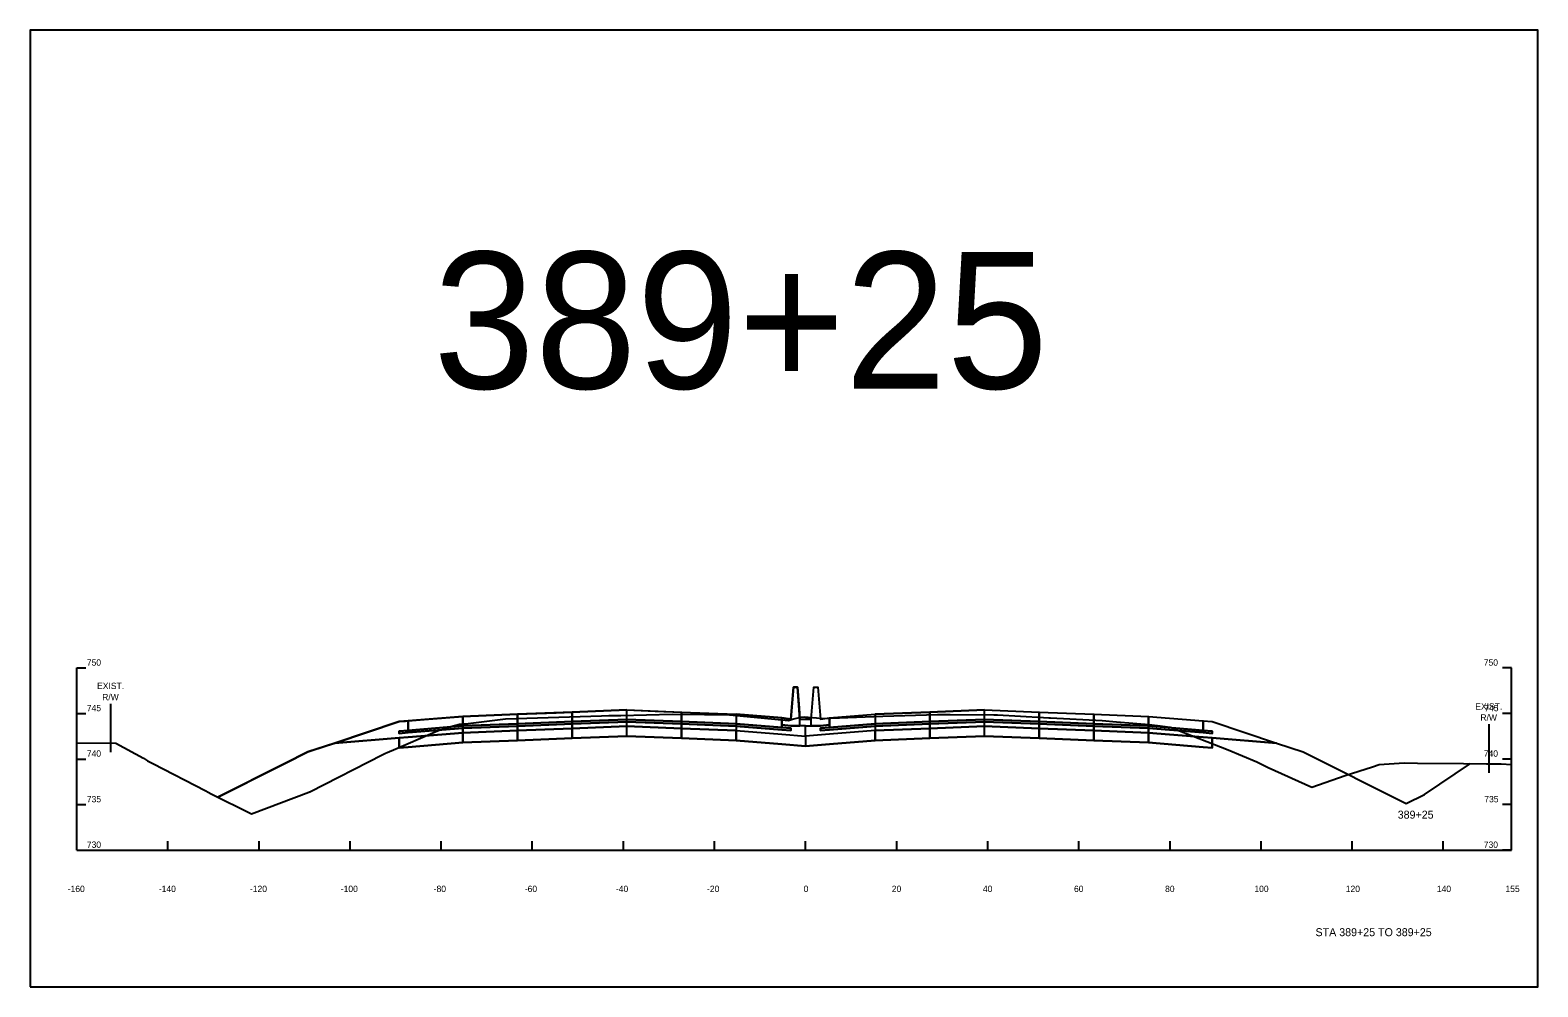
# Model space of a CAD drawing. Extents: x 0 to 2149228, y 0 to 2148913.
# Drawn here: x 2146915.4 to 2147246.4, y 2146375.1 to 2146585.1 of the extents above; entities that cross this region are included whole.
import ezdxf

# ---------------------------------------------------------------- set-up
doc = ezdxf.new("R2010")
doc.units = 0
for name, color, linetype in [('ADAMS CONST', 7, 'Continuous'), ('Default', 7, 'Continuous'), ('P_E_XS_Ground', 7, 'Continuous'), ('P_E_XS_RW', 7, 'Continuous'), ('P_MISC_TXT', 7, 'Continuous'), ('P_PROF_Grades', 7, 'Continuous'), ('P_RDWY_BarrierConc', 7, 'Continuous'), ('P_XS', 7, 'Continuous'), ('P_XS_Subgrade', 7, 'Continuous')]:
    doc.layers.add(name, color=color, linetype=linetype)

msp = doc.modelspace()

# ---------------------------------------------------------------- linework, layer by layer
at = {"layer": 'Default'}
msp.add_lwpolyline([(2146915.41, 2146375.06), (2147246.41, 2146375.06), (2147246.41, 2146585.06), (2146915.41, 2146585.06)], close=True, dxfattribs=at)
at = {"layer": 'P_E_XS_Ground'}
msp.add_lwpolyline([(2146925.66, 2146428.61), (2146934.2, 2146428.53), (2146940.27, 2146425.28), (2146941.18, 2146424.68), (2146942.36, 2146424.06), (2146953.95, 2146418.06), (2146954.5, 2146417.76), (2146955.13, 2146417.45), (2146963.99, 2146413), (2146976.57, 2146417.78), (2146976.76, 2146417.86), (2146976.78, 2146417.87), (2146992.81, 2146426.06), (2146993.42, 2146426.34), (2146993.76, 2146426.48), (2146994.3, 2146426.7), (2146995.21, 2146427.07), (2147004.34, 2146431.01), (2147005.19, 2146431.38), (2147005.23, 2146431.39), (2147006.79, 2146431.76), (2147007.23, 2146431.96), (2147007.77, 2146432.18), (2147009.67, 2146432.73), (2147011.59, 2146432.89), (2147019.78, 2146433.89), (2147040.84, 2146434.52), (2147042.47, 2146434.59), (2147042.6, 2146434.59), (2147044.28, 2146434.63), (2147045.08, 2146434.65), (2147056.33, 2146434.91), (2147063.48, 2146434.84), (2147068.24, 2146434.82), (2147076.66, 2146434.03), (2147081.88, 2146433.53), (2147082.8, 2146433.78), (2147084.58, 2146434.28), (2147085.47, 2146434.34), (2147086.25, 2146434.24), (2147088.05, 2146434.11), (2147089.26, 2146433.96), (2147100.6, 2146434.42), (2147102.61, 2146434.5), (2147114.63, 2146434.86), (2147114.89, 2146434.87), (2147117.39, 2146434.85), (2147126.96, 2146434.76), (2147127.81, 2146434.73), (2147137.89, 2146434.18), (2147139.06, 2146434.11), (2147139.42, 2146434.09), (2147150.78, 2146433.51), (2147153.94, 2146433.22), (2147161.07, 2146432.66), (2147163.48, 2146432.38), (2147165.7, 2146432.07), (2147178.43, 2146427.05), (2147184.73, 2146424.44), (2147187.2, 2146423.2), (2147196.79, 2146418.89), (2147204.12, 2146421.44), (2147210.1, 2146423.32), (2147211.59, 2146423.83), (2147217.08, 2146424.2), (2147219.96, 2146424.17), (2147230.11, 2146424.05), (2147235.12, 2146424.04), (2147238.39, 2146424), (2147240.66, 2146423.86)], dxfattribs=at)
at = {"layer": 'P_E_XS_RW'}
for p, q in [((2146933.09, 2146437.2), (2146933.09, 2146426.54)), ((2147235.66, 2146432.69), (2147235.66, 2146422.03))]:
    msp.add_line(p, q, dxfattribs=at)
at = {"layer": 'P_RDWY_BarrierConc'}
for p, q in [((2146925.66, 2146405.06), (2146925.66, 2146445.06)), ((2146925.66, 2146445.06), (2146927.66, 2146445.06)), ((2147240.66, 2146445.06), (2147238.66, 2146445.06)), ((2147240.66, 2146405.06), (2147240.66, 2146445.06)), ((2146925.66, 2146435.06), (2146927.66, 2146435.06)), ((2147240.66, 2146435.06), (2147238.66, 2146435.06)), ((2146925.66, 2146425.06), (2146927.66, 2146425.06)), ((2147240.66, 2146425.06), (2147238.66, 2146425.06)), ((2146925.66, 2146415.06), (2146927.66, 2146415.06)), ((2147240.66, 2146415.06), (2147238.66, 2146415.06)), ((2146925.66, 2146405.06), (2146925.66, 2146407.06)), ((2146945.66, 2146405.06), (2146945.66, 2146407.06)), ((2146965.66, 2146405.06), (2146965.66, 2146407.06)), ((2146985.66, 2146405.06), (2146985.66, 2146407.06)), ((2147005.66, 2146405.06), (2147005.66, 2146407.06)), ((2147025.66, 2146405.06), (2147025.66, 2146407.06)), ((2147045.66, 2146405.06), (2147045.66, 2146407.06)), ((2147065.66, 2146405.06), (2147065.66, 2146407.06)), ((2147085.66, 2146405.06), (2147085.66, 2146407.06)), ((2147105.66, 2146405.06), (2147105.66, 2146407.06)), ((2147125.66, 2146405.06), (2147125.66, 2146407.06)), ((2147145.66, 2146405.06), (2147145.66, 2146407.06)), ((2147165.66, 2146405.06), (2147165.66, 2146407.06)), ((2147185.66, 2146405.06), (2147185.66, 2146407.06)), ((2147205.66, 2146405.06), (2147205.66, 2146407.06)), ((2147225.66, 2146405.06), (2147225.66, 2146407.06)), ((2147240.66, 2146405.06), (2147240.66, 2146407.06)), ((2146925.66, 2146405.06), (2146927.66, 2146405.06)), ((2146925.66, 2146405.06), (2147240.66, 2146405.06)), ((2147240.66, 2146405.06), (2147238.66, 2146405.06))]:
    msp.add_line(p, q, dxfattribs=at)
at = {"layer": 'P_XS'}
for points in [[(2146956.6, 2146416.71), (2146969.69, 2146423.26), (2146971.32, 2146424.07), (2146971.46, 2146424.14), (2146976.41, 2146426.62), (2146980.62, 2146428.02), (2146982.28, 2146428.57), (2146996.41, 2146433.29), (2146997.83, 2146433.4), (2146998.41, 2146433.45), (2147001.92, 2146433.73), (2147010.41, 2146434.41), (2147022.41, 2146434.89), (2147030.92, 2146435.23), (2147034.41, 2146435.37), (2147046.41, 2146435.85), (2147052.6, 2146435.6), (2147058.41, 2146435.37), (2147070.41, 2146434.89), (2147080.41, 2146434.09), (2147081.76, 2146433.92), (2147082.41, 2146433.84), (2147082.98, 2146440.84), (2147083.85, 2146440.84), (2147084.22, 2146436.23), (2147084.41, 2146433.84), (2147085.66, 2146433.84)], [(2147085.66, 2146433.84), (2147086.91, 2146433.84), (2147087.48, 2146440.84), (2147088.35, 2146440.84), (2147088.91, 2146433.84), (2147090.91, 2146434.09), (2147100.91, 2146434.89), (2147112.91, 2146435.37), (2147124.91, 2146435.85), (2147136.91, 2146435.37), (2147148.91, 2146434.89), (2147160.91, 2146434.41), (2147172.91, 2146433.45), (2147174.91, 2146433.29), (2147189.06, 2146428.57), (2147194.91, 2146426.62), (2147217.54, 2146415.31), (2147221.54, 2146417.31), (2147231.65, 2146424.05)], [(2147085.66, 2146433.84), (2147086.91, 2146433.84), (2147085.66, 2146433.84)]]:
    msp.add_lwpolyline(points, dxfattribs=at)
for points in [[(2147084.41, 2146433.84), (2147083.85, 2146440.84), (2147082.98, 2146440.84), (2147082.41, 2146433.84), (2147080.41, 2146434.09), (2147080.41, 2146432.59), (2147082.41, 2146432.34), (2147084.41, 2146432.34)], [(2147086.91, 2146433.84), (2147087.48, 2146440.84), (2147088.35, 2146440.84), (2147088.91, 2146433.84), (2147090.91, 2146434.09), (2147090.91, 2146432.59), (2147088.91, 2146432.34), (2147086.91, 2146432.34)], [(2147046.41, 2146435.85), (2147034.41, 2146435.37), (2147034.41, 2146433.28), (2147046.41, 2146433.76)], [(2147046.41, 2146435.85), (2147058.41, 2146435.37), (2147058.41, 2146433.28), (2147046.41, 2146433.76)], [(2147124.91, 2146435.85), (2147112.91, 2146435.37), (2147112.91, 2146433.28), (2147124.91, 2146433.76)], [(2147124.91, 2146435.85), (2147136.91, 2146435.37), (2147136.91, 2146433.28), (2147124.91, 2146433.76)], [(2147010.41, 2146431.82), (2146998.41, 2146430.86), (2146996.41, 2146430.7), (2146996.41, 2146431.2), (2146998.41, 2146431.36), (2146998.41, 2146433.45), (2146996.41, 2146433.29), (2146982.28, 2146428.57), (2146996.41, 2146429.7), (2146998.41, 2146429.86), (2147010.41, 2146430.82)], [(2147010.41, 2146434.41), (2146998.41, 2146433.45), (2146998.41, 2146431.36), (2147010.41, 2146432.32)], [(2147022.41, 2146434.89), (2147010.41, 2146434.41), (2147010.41, 2146432.32), (2147022.41, 2146432.8)], [(2147022.41, 2146432.8), (2147010.41, 2146432.32), (2147010.41, 2146431.82), (2147022.41, 2146432.3)], [(2147034.41, 2146435.37), (2147022.41, 2146434.89), (2147022.41, 2146432.8), (2147034.41, 2146433.28)], [(2147034.41, 2146433.28), (2147022.41, 2146432.8), (2147022.41, 2146432.3), (2147034.41, 2146432.78)], [(2147034.41, 2146432.78), (2147022.41, 2146432.3), (2147022.41, 2146431.3), (2147034.41, 2146431.78)], [(2147046.41, 2146433.76), (2147034.41, 2146433.28), (2147034.41, 2146432.78), (2147046.41, 2146433.26)], [(2147046.41, 2146433.26), (2147034.41, 2146432.78), (2147034.41, 2146431.78), (2147046.41, 2146432.26)], [(2147046.41, 2146433.76), (2147058.41, 2146433.28), (2147058.41, 2146432.78), (2147046.41, 2146433.26)], [(2147046.41, 2146433.26), (2147058.41, 2146432.78), (2147058.41, 2146431.78), (2147046.41, 2146432.26)], [(2147058.41, 2146435.37), (2147070.41, 2146434.89), (2147070.41, 2146432.8), (2147058.41, 2146433.28)], [(2147058.41, 2146433.28), (2147070.41, 2146432.8), (2147070.41, 2146432.3), (2147058.41, 2146432.78)], [(2147058.41, 2146432.78), (2147070.41, 2146432.3), (2147070.41, 2146431.3), (2147058.41, 2146431.78)], [(2147080.41, 2146432), (2147080.41, 2146434.09), (2147070.41, 2146434.89), (2147070.41, 2146432.8)], [(2147080.41, 2146431.5), (2147082.41, 2146431.34), (2147082.41, 2146431.84), (2147080.41, 2146432), (2147070.41, 2146432.8), (2147070.41, 2146432.3)], [(2147080.41, 2146431.5), (2147070.41, 2146432.3), (2147070.41, 2146431.3), (2147080.41, 2146430.5), (2147085.66, 2146430.08), (2147085.66, 2146432.34), (2147082.41, 2146432.34), (2147080.41, 2146432.59), (2147080.41, 2146432), (2147082.41, 2146431.84), (2147082.41, 2146431.34)], [(2147090.91, 2146431.5), (2147100.91, 2146432.3), (2147100.91, 2146431.3), (2147090.91, 2146430.5), (2147085.66, 2146430.08), (2147085.66, 2146432.34), (2147088.91, 2146432.34), (2147090.91, 2146432.59), (2147090.91, 2146432), (2147088.91, 2146431.84), (2147088.91, 2146431.34)], [(2147090.91, 2146431.5), (2147088.91, 2146431.34), (2147088.91, 2146431.84), (2147090.91, 2146432), (2147100.91, 2146432.8), (2147100.91, 2146432.3)], [(2147090.91, 2146432), (2147090.91, 2146434.09), (2147100.91, 2146434.89), (2147100.91, 2146432.8)], [(2147112.91, 2146435.37), (2147100.91, 2146434.89), (2147100.91, 2146432.8), (2147112.91, 2146433.28)], [(2147112.91, 2146433.28), (2147100.91, 2146432.8), (2147100.91, 2146432.3), (2147112.91, 2146432.78)], [(2147112.91, 2146432.78), (2147100.91, 2146432.3), (2147100.91, 2146431.3), (2147112.91, 2146431.78)], [(2147124.91, 2146433.76), (2147112.91, 2146433.28), (2147112.91, 2146432.78), (2147124.91, 2146433.26)], [(2147124.91, 2146433.26), (2147112.91, 2146432.78), (2147112.91, 2146431.78), (2147124.91, 2146432.26)], [(2147124.91, 2146433.76), (2147136.91, 2146433.28), (2147136.91, 2146432.78), (2147124.91, 2146433.26)], [(2147124.91, 2146433.26), (2147136.91, 2146432.78), (2147136.91, 2146431.78), (2147124.91, 2146432.26)], [(2147136.91, 2146435.37), (2147148.91, 2146434.89), (2147148.91, 2146432.8), (2147136.91, 2146433.28)], [(2147136.91, 2146433.28), (2147148.91, 2146432.8), (2147148.91, 2146432.3), (2147136.91, 2146432.78)], [(2147136.91, 2146432.78), (2147148.91, 2146432.3), (2147148.91, 2146431.3), (2147136.91, 2146431.78)], [(2147148.91, 2146434.89), (2147160.91, 2146434.41), (2147160.91, 2146432.32), (2147148.91, 2146432.8)], [(2147148.91, 2146432.8), (2147160.91, 2146432.32), (2147160.91, 2146431.82), (2147148.91, 2146432.3)], [(2147160.91, 2146434.41), (2147172.91, 2146433.45), (2147172.91, 2146431.36), (2147160.91, 2146432.32)], [(2147160.91, 2146431.82), (2147172.91, 2146430.86), (2147174.91, 2146430.7), (2147174.91, 2146431.2), (2147172.91, 2146431.36), (2147172.91, 2146433.45), (2147174.91, 2146433.29), (2147189.06, 2146428.57), (2147174.91, 2146429.7), (2147172.91, 2146429.86), (2147160.91, 2146430.82)], [(2147010.41, 2146432.32), (2146998.41, 2146431.36), (2146996.41, 2146431.2), (2146996.41, 2146430.7), (2146998.41, 2146430.86), (2147010.41, 2146431.82)], [(2147010.41, 2146430.82), (2146998.41, 2146429.86), (2146996.41, 2146429.7), (2146996.41, 2146427.54), (2146998.41, 2146427.7), (2147010.41, 2146428.66)], [(2147022.41, 2146432.3), (2147010.41, 2146431.82), (2147010.41, 2146430.82), (2147022.41, 2146431.3)], [(2147022.41, 2146431.3), (2147010.41, 2146430.82), (2147010.41, 2146428.66), (2147022.41, 2146429.14)], [(2147034.41, 2146431.78), (2147022.41, 2146431.3), (2147022.41, 2146429.14), (2147034.41, 2146429.62)], [(2147046.41, 2146432.26), (2147034.41, 2146431.78), (2147034.41, 2146429.62), (2147046.41, 2146430.1)], [(2147046.41, 2146432.26), (2147058.41, 2146431.78), (2147058.41, 2146429.62), (2147046.41, 2146430.1)], [(2147070.41, 2146429.14), (2147058.41, 2146429.62), (2147058.41, 2146431.78), (2147070.41, 2146431.3)], [(2147070.41, 2146431.3), (2147080.41, 2146430.5), (2147085.66, 2146430.08), (2147085.66, 2146427.92), (2147080.41, 2146428.34), (2147070.41, 2146429.14)], [(2147100.91, 2146431.3), (2147090.91, 2146430.5), (2147085.66, 2146430.08), (2147085.66, 2146427.92), (2147090.91, 2146428.34), (2147100.91, 2146429.14)], [(2147112.91, 2146431.78), (2147100.91, 2146431.3), (2147100.91, 2146429.14), (2147112.91, 2146429.62)], [(2147124.91, 2146432.26), (2147112.91, 2146431.78), (2147112.91, 2146429.62), (2147124.91, 2146430.1)], [(2147124.91, 2146432.26), (2147136.91, 2146431.78), (2147136.91, 2146429.62), (2147124.91, 2146430.1)], [(2147136.91, 2146431.78), (2147148.91, 2146431.3), (2147148.91, 2146429.14), (2147136.91, 2146429.62)], [(2147148.91, 2146432.3), (2147160.91, 2146431.82), (2147160.91, 2146430.82), (2147148.91, 2146431.3)], [(2147148.91, 2146431.3), (2147160.91, 2146430.82), (2147160.91, 2146428.66), (2147148.91, 2146429.14)], [(2147160.91, 2146432.32), (2147172.91, 2146431.36), (2147174.91, 2146431.2), (2147174.91, 2146430.7), (2147172.91, 2146430.86), (2147160.91, 2146431.82)], [(2147174.91, 2146427.54), (2147172.91, 2146427.7), (2147160.91, 2146428.66), (2147160.91, 2146430.82), (2147172.91, 2146429.86), (2147174.91, 2146429.7)]]:
    msp.add_lwpolyline(points, close=True, dxfattribs=at)
at = {"layer": 'P_XS_Subgrade'}
for points in [[(2147022.41, 2146429.14), (2147010.41, 2146428.66), (2146998.41, 2146427.7), (2146996.41, 2146427.54), (2146996.41, 2146429.7), (2146982.28, 2146428.57), (2146996.41, 2146429.7), (2146996.41, 2146427.54), (2146998.41, 2146427.7)], [(2147034.41, 2146429.62), (2147022.41, 2146429.14), (2147010.41, 2146428.66)], [(2147046.41, 2146430.1), (2147034.41, 2146429.62)], [(2147046.41, 2146430.1), (2147058.41, 2146429.62), (2147046.41, 2146430.1)], [(2147058.41, 2146429.62), (2147070.41, 2146429.14), (2147058.41, 2146429.62)], [(2147112.91, 2146429.62), (2147100.91, 2146429.14), (2147112.91, 2146429.62)], [(2147124.91, 2146430.1), (2147112.91, 2146429.62), (2147124.91, 2146430.1)], [(2147124.91, 2146430.1), (2147136.91, 2146429.62)], [(2147136.91, 2146429.62), (2147148.91, 2146429.14), (2147136.91, 2146429.62)], [(2147148.91, 2146429.14), (2147160.91, 2146428.66), (2147172.91, 2146427.7), (2147174.91, 2146427.54), (2147174.91, 2146429.7), (2147189.06, 2146428.57)], [(2146982.28, 2146428.57), (2146976.41, 2146426.62), (2146971.32, 2146424.07)], [(2147189.06, 2146428.57), (2147194.91, 2146426.62), (2147217.54, 2146415.31)], [(2146971.32, 2146424.07), (2146956.6, 2146416.71)], [(2147221.54, 2146417.31), (2147231.65, 2146424.05)], [(2147217.54, 2146415.31), (2147221.54, 2146417.31)]]:
    msp.add_lwpolyline(points, dxfattribs=at)
for points in [[(2147070.41, 2146429.14), (2147080.41, 2146428.34), (2147085.66, 2146427.92), (2147080.41, 2146428.34)], [(2147090.91, 2146428.34), (2147100.91, 2146429.14), (2147090.91, 2146428.34), (2147085.66, 2146427.92)]]:
    msp.add_lwpolyline(points, close=True, dxfattribs=at)

# ---------------------------------------------------------------- texts
at = {"layer": 'ADAMS CONST'}
msp.add_text('389+25', height=30, dxfattribs=at).set_placement((2147003.92, 2146506.38))
at = {"layer": 'Default'}
for p in [(2147022.38, 2146429.09), (2147046.38, 2146430.05), (2147070.38, 2146429.09), (2147100.88, 2146429.09), (2147124.88, 2146430.05), (2146976.38, 2146426.57), (2146982.24, 2146428.52), (2146996.38, 2146427.49), (2147085.63, 2146427.87), (2147085.63, 2146427.87), (2147090.88, 2146428.29), (2147160.88, 2146428.61), (2147174.88, 2146427.49), (2147189.03, 2146428.52), (2147194.88, 2146426.57), (2146971.28, 2146424.02), (2146971.28, 2146424.02), (2147231.62, 2146424), (2146956.57, 2146416.66), (2147221.51, 2146417.26), (2147217.51, 2146415.26)]:
    msp.add_text('+', height=0.1, dxfattribs=at).set_placement(p)
at = {"layer": 'P_E_XS_RW'}
for s, p in [('EXIST.', (2146930.11, 2146440.42)), ('R/W', (2146931.23, 2146437.97)), ('EXIST.', (2147232.68, 2146435.91)), ('R/W', (2147233.8, 2146433.46))]:
    msp.add_text(s, height=1.4, rotation=360, dxfattribs=at).set_placement(p)
at = {"layer": 'P_MISC_TXT'}
for s, p in [('389+25', (2147215.65, 2146411.98)), ('STA 389+25 TO 389+25', (2147197.61, 2146386.18))]:
    msp.add_text(s, height=1.75, dxfattribs=at).set_placement(p)
at = {"layer": 'P_PROF_Grades'}
for s, p in [('750', (2146927.86, 2146445.56)), ('750', (2147234.54, 2146445.56)), ('745', (2146927.86, 2146435.56)), ('745', (2147234.66, 2146435.56)), ('740', (2146927.86, 2146425.56)), ('740', (2147234.54, 2146425.56)), ('735', (2146927.86, 2146415.56)), ('735', (2147234.66, 2146415.56)), ('730', (2146927.86, 2146405.56)), ('730', (2147234.54, 2146405.56)), ('-160', (2146923.66, 2146395.86)), ('-140', (2146943.66, 2146395.86)), ('-120', (2146963.66, 2146395.86)), ('-100', (2146983.61, 2146395.86)), ('-80', (2147004.01, 2146395.86)), ('-60', (2147024.01, 2146395.86)), ('-40', (2147044.01, 2146395.86)), ('-20', (2147064.01, 2146395.86)), ('0', (2147085.21, 2146395.86)), ('20', (2147104.58, 2146395.86)), ('40', (2147124.58, 2146395.86)), ('60', (2147144.58, 2146395.86)), ('80', (2147164.58, 2146395.86)), ('100', (2147184.18, 2146395.86)), ('120', (2147204.24, 2146395.86)), ('140', (2147224.24, 2146395.86)), ('155', (2147239.3, 2146395.86))]:
    msp.add_text(s, height=1.4, dxfattribs=at).set_placement(p)
at = {"layer": 'P_RDWY_BarrierConc'}
msp.add_text('-', height=0.0001, dxfattribs=at).set_placement((2146925.66, 2146405.06))

doc.saveas('drawing.dxf')
